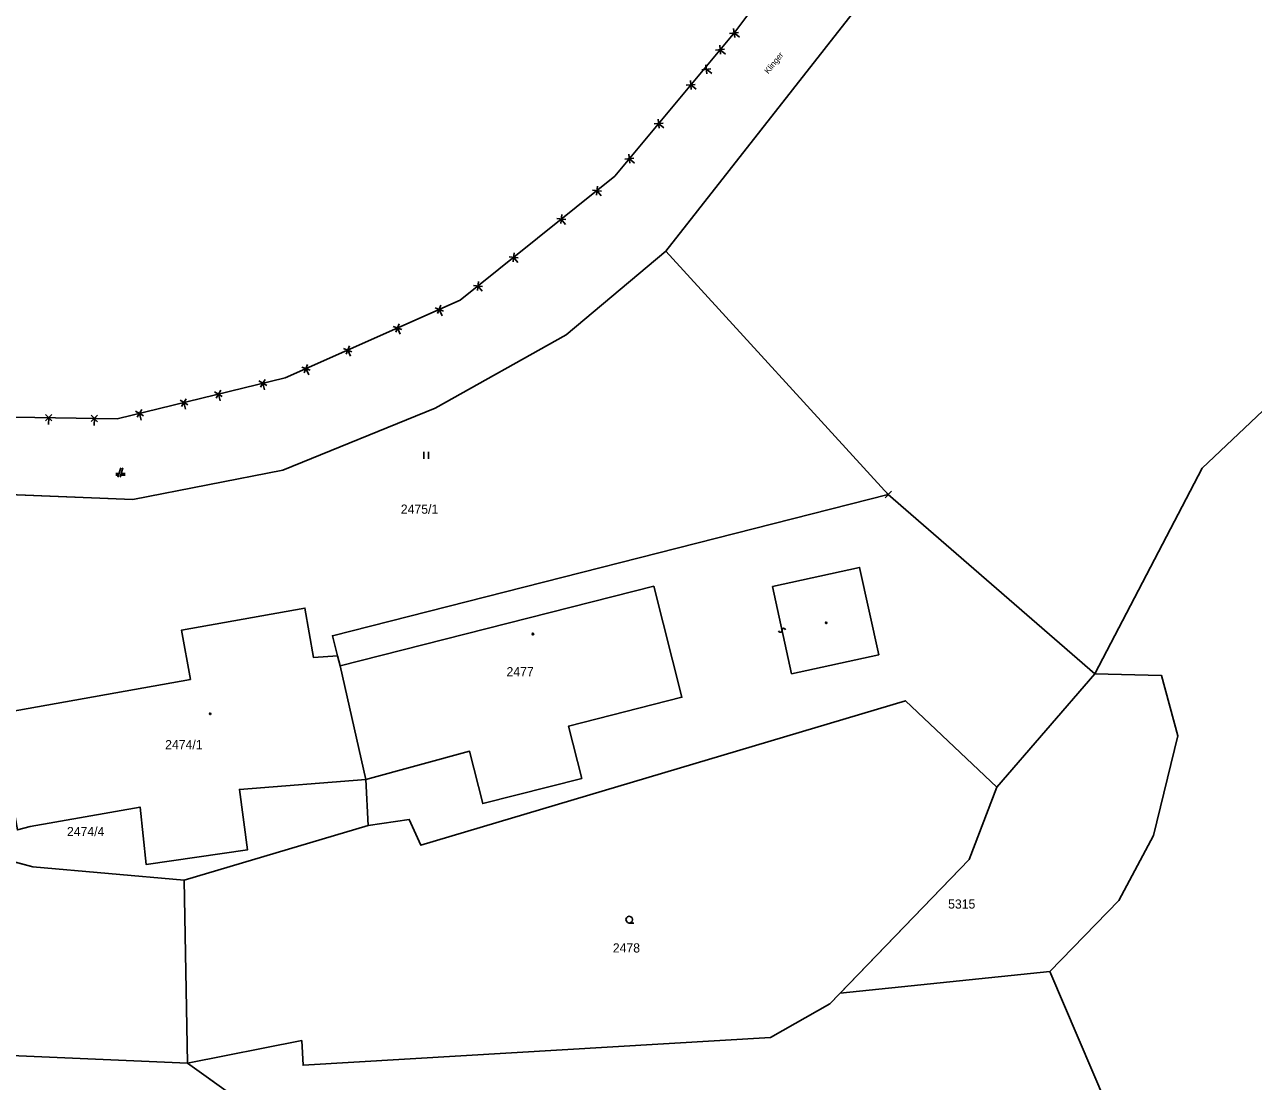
# Model space of a CAD drawing. Extents: x -439750 to -439180, y -1258684 to -1258308.
# Drawn here: x -439598.2 to -439544.4, y -1258486.3 to -1258440.1 of the extents above; entities that cross this region are included whole.
import ezdxf

# ---------------------------------------------------------------- set-up
doc = ezdxf.new("R2010")
doc.units = 0
for name, color, linetype in [('KATASTER', 7, 'Continuous'), ('POPIS', 7, 'Continuous'), ('UOV', 7, 'Continuous')]:
    doc.layers.add(name, color=color, linetype=linetype)

# ---------------------------------------------------------------- blocks, each defined once
blk = doc.blocks.new('402')
blk.add_lwpolyline([(0.09, 0.15), (0.18, 0), (0.09, -0.15), (-0.09, -0.15), (-0.18, 0), (-0.09, 0.15), (0.09, 0.15)])
blk = doc.blocks.new('304')
blk.add_lwpolyline([(0, 0), (-0.38, 0.1), (-0.65, 0.37), (-0.75, 0.74), (-0.65, 1.11), (-0.38, 1.38), (-0.01, 1.48), (0.36, 1.38), (0.63, 1.11), (0.73, 0.73), (0.63, 0.35), (0.36, 0.08), (-0.02, -0.02), (0.98, -0.02)])
blk = doc.blocks.new('CESTA')
for p, q in [((-0.32, 0.8), (-1, 0.8)), ((-1, 0.4), (-0.46, 0.4)), ((0.1, 2), (-0.6, 0)), ((-0.1, 0), (0.5, 2)), ((0.02, 0.4), (1, 0.4)), ((1, 0.8), (0.14, 0.8))]:
    blk.add_line(p, q)
blk = doc.blocks.new('POINT_DISPLAY')
for p, q in [((-0.14, -0.14), (0.14, 0.14)), ((-0.14, 0.14), (0.14, -0.14))]:
    blk.add_line(p, q)
blk = doc.blocks.new('306')
for p, q in [((-0.5, 1.5), (-0.5, 0)), ((0.5, 0), (0.5, 1.5))]:
    blk.add_line(p, q)
blk = doc.blocks.new('2182')
blk.add_lwpolyline([(0.05, 0.75), (-0.26, 0.64), (-0.37, 0.34), (-0.23, 0.09), (0.27, -0.11), (0.37, -0.41), (0.21, -0.68), (-0.05, -0.75)])
blk = doc.blocks.new('2072')
for p, q in [((-4.3, 0.7), (-5.7, -0.7)), ((-5.7, 0.7), (-4.3, -0.7)), ((-5, 0), (-5, -1.5)), ((4.3, 0.7), (5.7, -0.7)), ((5.7, 0.7), (4.3, -0.7)), ((5, 0), (5, -1.5))]:
    blk.add_line(p, q)

msp = doc.modelspace()

# ---------------------------------------------------------------- linework, layer by layer
at = {"layer": 'KATASTER'}
for p, q in [((-439564.6, -1258468.47), (-439565.44, -1258464.65)), ((-439560.78, -1258467.63), (-439564.6, -1258468.47))]:
    msp.add_line(p, q, dxfattribs=at)
for points in [[(-439680.32, -1258364.89), (-439664.32, -1258378.2), (-439607.94, -1258413.98), (-439588.39, -1258414.26), (-439581.78, -1258408.62), (-439578.76, -1258414.75), (-439570.17, -1258432.21), (-439566.51, -1258439.64), (-439567.09, -1258440.4), (-439572.34, -1258446.7), (-439579.1, -1258452.12), (-439586.76, -1258455.52), (-439594.1, -1258457.31), (-439604.91, -1258457.14), (-439610.82, -1258457.46), (-439627.78, -1258463.49), (-439614.4, -1258450.89), (-439625.47, -1258430.92), (-439655.75, -1258405.12), (-439680.64, -1258393.46)], [(-439529.05, -1258372.98), (-439583.01, -1258405.44), (-439581.78, -1258408.62), (-439578.76, -1258414.75), (-439570.17, -1258432.21), (-439566.51, -1258439.64), (-439567.09, -1258440.4), (-439572.34, -1258446.7), (-439579.1, -1258452.12), (-439586.76, -1258455.52), (-439594.1, -1258457.31), (-439604.91, -1258457.14), (-439610.82, -1258457.46), (-439627.78, -1258463.49), (-439614.4, -1258450.89), (-439625.47, -1258430.92), (-439655.75, -1258405.12), (-439680.64, -1258393.46)], [(-439680.64, -1258393.46), (-439655.75, -1258405.12), (-439625.47, -1258430.92), (-439614.4, -1258450.89), (-439627.78, -1258463.49), (-439610.82, -1258457.46), (-439604.91, -1258457.14), (-439594.1, -1258457.31), (-439586.76, -1258455.52), (-439579.1, -1258452.12), (-439572.34, -1258446.7), (-439567.09, -1258440.4), (-439566.51, -1258439.64), (-439570.17, -1258432.21), (-439578.76, -1258414.75), (-439581.78, -1258408.62), (-439583.01, -1258405.44), (-439529.05, -1258372.98)], [(-439660.49, -1258516.44), (-439665.91, -1258502.4), (-439666.82, -1258496.88), (-439665.48, -1258490.84), (-439662.74, -1258486.44), (-439657.56, -1258481.06), (-439653.51, -1258478.38), (-439649.29, -1258475.58), (-439627.78, -1258463.49), (-439610.82, -1258457.46), (-439604.91, -1258457.14), (-439594.1, -1258457.31), (-439586.76, -1258455.52), (-439579.1, -1258452.12), (-439572.34, -1258446.7), (-439567.09, -1258440.4), (-439566.51, -1258439.64), (-439564.85, -1258437.53), (-439556.57, -1258427.01), (-439547.65, -1258418.05), (-439537.73, -1258410.35)], [(-439536.05, -1258413.64), (-439546.05, -1258421.31), (-439554.71, -1258430.36), (-439570.11, -1258449.98), (-439574.47, -1258453.63), (-439580.2, -1258456.85), (-439586.86, -1258459.56), (-439593.42, -1258460.84), (-439598.86, -1258460.62), (-439604.63, -1258460.39), (-439610.67, -1258460.8), (-439615.1, -1258461.87), (-439623.26, -1258465.49), (-439629.03, -1258468.61), (-439635.72, -1258471.93), (-439658.88, -1258489.54), (-439659.88, -1258488.91), (-439662.11, -1258495.3), (-439662.28, -1258501.2), (-439658.45, -1258512.88)], [(-439541.07, -1258454.21), (-439546.64, -1258459.47), (-439551.33, -1258468.47), (-439560.37, -1258460.62), (-439570.11, -1258449.98), (-439554.71, -1258430.36), (-439546.05, -1258421.31), (-439536.05, -1258413.64)], [(-439538.17, -1258484.88), (-439548.5, -1258497.7), (-439564.69, -1258504.32), (-439591.03, -1258485.49), (-439586.03, -1258484.5), (-439585.97, -1258485.58), (-439565.52, -1258484.37), (-439562.93, -1258482.9), (-439556.83, -1258476.59), (-439555.63, -1258473.42), (-439551.33, -1258468.47), (-439546.64, -1258459.47), (-439541.07, -1258454.21)], [(-439565.44, -1258464.65), (-439561.63, -1258463.81), (-439560.78, -1258467.63)], [(-439584.35, -1258468.11), (-439570.63, -1258464.63), (-439569.4, -1258469.49), (-439574.36, -1258470.75), (-439573.78, -1258473.04), (-439578.11, -1258474.14), (-439578.69, -1258471.85), (-439583.22, -1258473.09)]]:
    msp.add_lwpolyline(points, dxfattribs=at)
for points in [[(-439580.2, -1258456.85), (-439574.47, -1258453.63), (-439570.11, -1258449.98), (-439560.37, -1258460.62), (-439584.69, -1258466.8), (-439584.46, -1258467.67), (-439585.51, -1258467.75), (-439585.89, -1258465.59), (-439591.29, -1258466.55), (-439590.9, -1258468.71), (-439598.81, -1258470.12), (-439599.97, -1258469.68), (-439600.45, -1258469.56), (-439598.86, -1258460.62), (-439593.42, -1258460.84), (-439586.86, -1258459.56)], [(-439584.69, -1258466.8), (-439560.37, -1258460.62), (-439551.33, -1258468.47), (-439555.63, -1258473.42), (-439559.62, -1258469.64), (-439580.82, -1258475.96), (-439581.33, -1258474.83), (-439583.13, -1258475.1), (-439583.22, -1258473.09), (-439584.35, -1258468.11), (-439584.46, -1258467.67)], [(-439591.29, -1258466.55), (-439585.89, -1258465.59), (-439585.51, -1258467.75), (-439584.46, -1258467.67), (-439584.35, -1258468.11), (-439583.22, -1258473.09), (-439588.76, -1258473.52), (-439588.4, -1258476.16), (-439592.84, -1258476.8), (-439593.1, -1258474.29), (-439597.91, -1258475.14), (-439598.47, -1258475.29), (-439599.38, -1258470.22), (-439598.81, -1258470.12), (-439590.9, -1258468.71)], [(-439635.72, -1258471.93), (-439629.03, -1258468.61), (-439601.7, -1258475.86), (-439597.79, -1258476.9), (-439591.18, -1258477.49), (-439591.03, -1258485.49), (-439606.15, -1258484.83), (-439620.34, -1258480.81)], [(-439583.22, -1258473.09), (-439583.13, -1258475.1), (-439591.18, -1258477.49), (-439597.79, -1258476.9), (-439601.7, -1258475.86), (-439601.25, -1258473.57), (-439600.48, -1258469.73), (-439600.45, -1258469.56), (-439599.97, -1258469.68), (-439598.81, -1258470.12), (-439599.38, -1258470.22), (-439598.47, -1258475.29), (-439597.91, -1258475.14), (-439593.1, -1258474.29), (-439592.84, -1258476.8), (-439588.4, -1258476.16), (-439588.76, -1258473.52)], [(-439583.13, -1258475.1), (-439581.33, -1258474.83), (-439580.82, -1258475.96), (-439559.62, -1258469.64), (-439555.63, -1258473.42), (-439556.83, -1258476.59), (-439562.93, -1258482.9), (-439565.52, -1258484.37), (-439585.97, -1258485.58), (-439586.03, -1258484.5), (-439591.03, -1258485.49), (-439591.18, -1258477.49)], [(-439658.88, -1258489.54), (-439635.72, -1258471.93), (-439620.34, -1258480.81), (-439606.15, -1258484.83), (-439591.03, -1258485.49), (-439564.69, -1258504.32), (-439589.36, -1258506.21), (-439597.08, -1258522.38), (-439597.45, -1258561.13), (-439640.46, -1258538.63)]]:
    msp.add_lwpolyline(points, close=True, dxfattribs=at)
at = {"layer": 'UOV'}
for points in [[(-439554.71, -1258430.36), (-439570.11, -1258449.98), (-439574.47, -1258453.63), (-439580.2, -1258456.85), (-439586.86, -1258459.56), (-439593.42, -1258460.84), (-439604.63, -1258460.39), (-439610.67, -1258460.8), (-439615.1, -1258461.87), (-439618.9, -1258463.55), (-439627.78, -1258463.49), (-439610.82, -1258457.46), (-439604.91, -1258457.14), (-439594.1, -1258457.31), (-439586.76, -1258455.52), (-439579.1, -1258452.12), (-439572.34, -1258446.7), (-439567.09, -1258440.4), (-439566.51, -1258439.64)], [(-439566.51, -1258439.64), (-439567.09, -1258440.4), (-439572.34, -1258446.7), (-439579.1, -1258452.12), (-439586.76, -1258455.52), (-439594.1, -1258457.31), (-439604.91, -1258457.14), (-439610.82, -1258457.46), (-439622.2, -1258458.24), (-439614.4, -1258450.89), (-439625.47, -1258430.92)]]:
    msp.add_lwpolyline(points, dxfattribs=at)
for points in [[(-439520.19, -1258486.95), (-439538.17, -1258484.88), (-439547.11, -1258495.98), (-439553.31, -1258481.48), (-439550.29, -1258478.38), (-439548.77, -1258475.54), (-439547.7, -1258471.18), (-439548.42, -1258468.53), (-439551.33, -1258468.47), (-439546.64, -1258459.47), (-439541.07, -1258454.21), (-439536.69, -1258451.87), (-439531.73, -1258450.85), (-439525.5, -1258450.78), (-439520.66, -1258452.66), (-439516.51, -1258455.4), (-439512.86, -1258458.3), (-439509.68, -1258462.08), (-439514.85, -1258480.71), (-439512.85, -1258480.94), (-439510.04, -1258487.61), (-439512.62, -1258492.23), (-439513.68, -1258492.23)], [(-439556.83, -1258476.59), (-439555.63, -1258473.42), (-439551.33, -1258468.47), (-439548.42, -1258468.53), (-439547.7, -1258471.18), (-439548.77, -1258475.54), (-439550.29, -1258478.38), (-439553.31, -1258481.48), (-439562.47, -1258482.43)], [(-439629.03, -1258468.61), (-439597.79, -1258476.9), (-439591.18, -1258477.49), (-439591.03, -1258485.49), (-439606.15, -1258484.83), (-439620.34, -1258480.81), (-439635.72, -1258471.93)], [(-439565.52, -1258484.37), (-439562.93, -1258482.9), (-439562.47, -1258482.43), (-439553.31, -1258481.48), (-439547.11, -1258495.98), (-439548.5, -1258497.7), (-439551.19, -1258498.8), (-439576.8, -1258495.66), (-439591.03, -1258485.49), (-439586.03, -1258484.5), (-439585.97, -1258485.58)]]:
    msp.add_lwpolyline(points, close=True, dxfattribs=at)

# ---------------------------------------------------------------- block references
at = {"layer": 'KATASTER'}
for name, p, xscale, yscale, rotation in [('2072', (-439567.723, -1258441.23), 0.2, 0.19999999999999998, 52.654821), ('2072', (-439568.37, -1258441.936), 0.20000000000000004, 0.2, 50.191103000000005), ('2072', (-439571.06, -1258445.164), 0.20000000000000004, 0.2, 50.191103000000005), ('2072', (-439573.9, -1258447.951), 0.2, 0.20000000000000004, 38.731947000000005), ('2072', (-439577.54, -1258450.869), 0.2, 0.20000000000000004, 38.731947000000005), ('2072', (-439580.928, -1258452.931), 0.2, 0.20000000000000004, 23.949635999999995), ('2072', (-439584.932, -1258454.709), 0.2, 0.20000000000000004, 23.949635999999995), ('2072', (-439588.703, -1258455.994), 0.2, 0.20000000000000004, 13.693691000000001), ('2072', (-439592.157, -1258456.836), 0.2, 0.20000000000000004, 13.693691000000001), ('2072', (-439596.1, -1258457.279), 0.2, 0.20000000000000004, -0.9273500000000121), ('2182', (-439565.02, -1258466.56), 0.20000000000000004, 0.2, 102.387558)]:
    msp.add_blockref(name, p, dxfattribs=dict(at, xscale=xscale, yscale=yscale, rotation=rotation))
at = {"layer": 'KATASTER', "xscale": 0.2, "yscale": 0.20000000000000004}
for name, p in [('306', (-439580.59, -1258459.06)), ('CESTA', (-439593.96, -1258459.86)), ('402', (-439563.09, -1258466.23)), ('402', (-439575.92, -1258466.72)), ('402', (-439590.04, -1258470.21)), ('304', (-439571.7, -1258479.36))]:
    msp.add_blockref(name, p, dxfattribs=at)
at = {"layer": 'KATASTER'}
msp.add_blockref('POINT_DISPLAY', (-439560.37, -1258460.62), dxfattribs=at)
msp.add_blockref('POINT_DISPLAY', (-439560.37, -1258460.62), dxfattribs=at)

# ---------------------------------------------------------------- texts
for s, p in [('2475/1', (-439581.695, -1258461.46)), ('2477', (-439577.072, -1258468.57)), ('2474/1', (-439592.005, -1258471.76)), ('2474/4', (-439596.301, -1258475.56)), ('2478', (-439572.422, -1258480.65))]:
    msp.add_text(s, height=0.4, dxfattribs=at).set_placement(p)
at = {"layer": 'POPIS'}
msp.add_text('Klinger', height=0.26, rotation=51.165, dxfattribs=at).set_placement((-439565.616, -1258442.247))
at = {"layer": 'UOV'}
msp.add_text('5315', height=0.4, dxfattribs=at).set_placement((-439557.754, -1258478.73))

doc.saveas('drawing.dxf')
